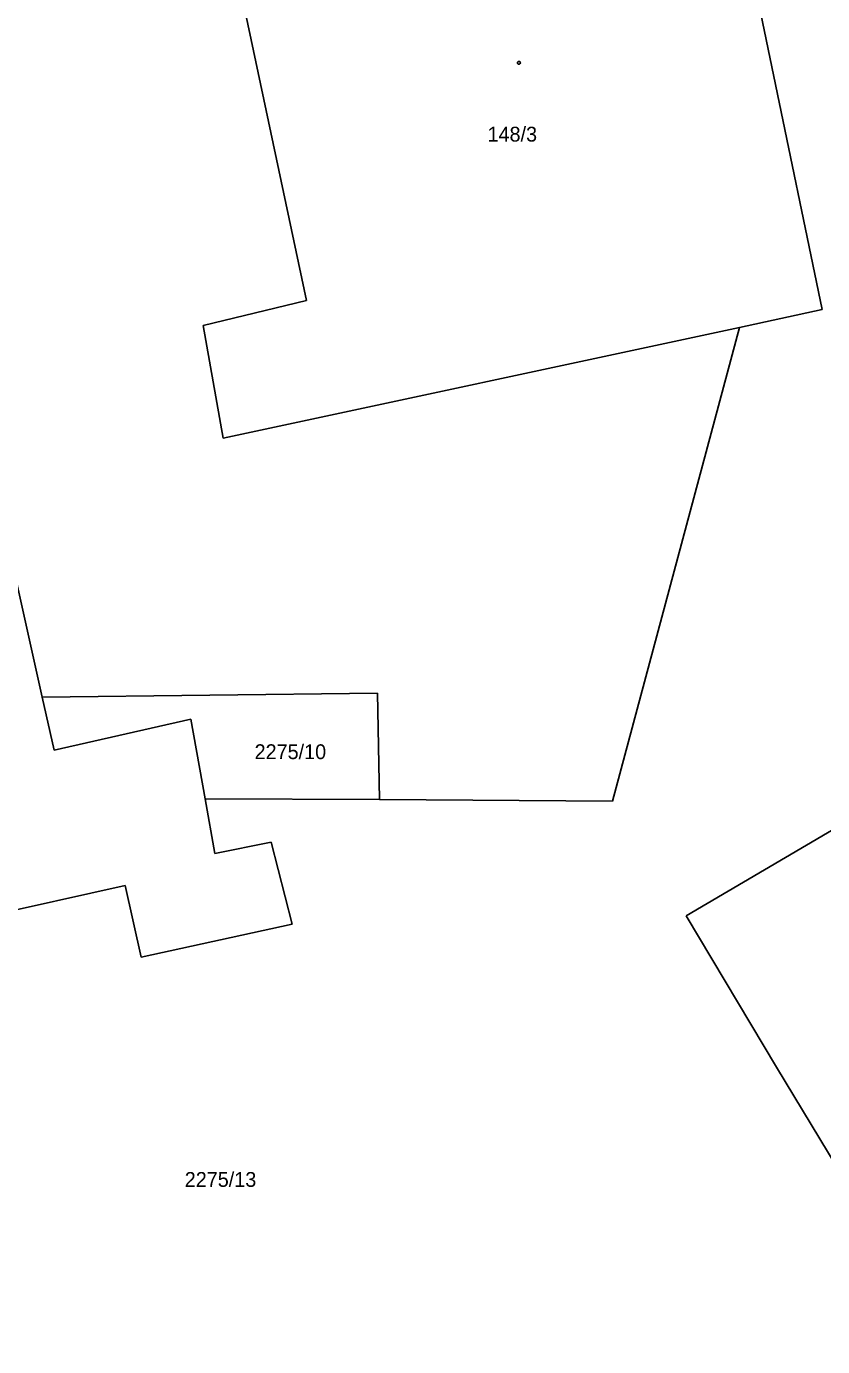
# Model space of a CAD drawing. Extents: x -747792 to -745414, y -1093712 to -1091463.
# Drawn here: x -746599.4 to -746553.7, y -1092850.4 to -1092774.6 of the extents above; entities that cross this region are included whole.
import ezdxf

# ---------------------------------------------------------------- set-up
doc = ezdxf.new("R2010")
doc.units = 0
for name, color, linetype in [('Koleje_dopravní prvky', 7, 'Continuous'), ('Ploty_opěrné zdi', 7, 'Continuous'), ('Stromy_porost', 7, 'Continuous')]:
    doc.layers.add(name, color=color, linetype=linetype)

msp = doc.modelspace()

# ---------------------------------------------------------------- linework, layer by layer
at = {"layer": 'Ploty_opěrné zdi'}
msp.add_lwpolyline([(-746571.09, -1092776.615), (-746571.04, -1092776.625), (-746571.015, -1092776.67), (-746571.005, -1092776.7), (-746571.015, -1092776.745), (-746571.055, -1092776.78), (-746571.09, -1092776.785), (-746571.135, -1092776.77), (-746571.165, -1092776.74), (-746571.175, -1092776.7), (-746571.165, -1092776.655), (-746571.125, -1092776.62)], close=True, dxfattribs=at)
at = {"layer": 'Stromy_porost'}
for points in [[(-746583.29, -1092790.35), (-746591.28, -1092752.64)], [(-746559.45, -1092762.98), (-746553.67, -1092790.87)], [(-746589.21, -1092791.79), (-746583.29, -1092790.35)], [(-746553.67, -1092790.87), (-746558.43, -1092791.89)], [(-746588.07, -1092798.26), (-746589.21, -1092791.79)], [(-746558.43, -1092791.89), (-746588.07, -1092798.26)], [(-746558.43, -1092791.89), (-746565.72, -1092819.1)], [(-746601.78, -1092798.21), (-746598.45, -1092813.12)], [(-746598.45, -1092813.12), (-746579.2, -1092812.89)], [(-746598.45, -1092813.12), (-746597.77, -1092816.16)], [(-746579.2, -1092812.89), (-746579.09, -1092819)], [(-746597.77, -1092816.16), (-746589.92, -1092814.39)], [(-746589.92, -1092814.39), (-746589.1, -1092818.96)], [(-746543.17, -1092814.93), (-746561.49, -1092825.68)], [(-746579.09, -1092819), (-746589.1, -1092818.96)], [(-746589.1, -1092818.96), (-746588.54, -1092822.1)], [(-746565.72, -1092819.1), (-746579.09, -1092819)], [(-746588.54, -1092822.1), (-746585.3, -1092821.44)], [(-746585.3, -1092821.44), (-746584.1, -1092826.16)], [(-746593.69, -1092823.93), (-746601.77, -1092825.73)], [(-746592.77, -1092828.05), (-746593.69, -1092823.93)], [(-746561.49, -1092825.68), (-746556.3, -1092834.36)], [(-746584.1, -1092826.16), (-746592.77, -1092828.05)], [(-746556.3, -1092834.36), (-746542.99, -1092856.39)]]:
    msp.add_lwpolyline(points, dxfattribs=at)

# ---------------------------------------------------------------- texts
at = {"layer": 'Koleje_dopravní prvky'}
for s, p in [('148/3', (-746572.889, -1092781.22)), ('2275/10', (-746586.262, -1092816.68)), ('2275/13', (-746590.272, -1092841.24))]:
    msp.add_text(s, height=0.85, dxfattribs=at).set_placement(p)

doc.saveas('drawing.dxf')
